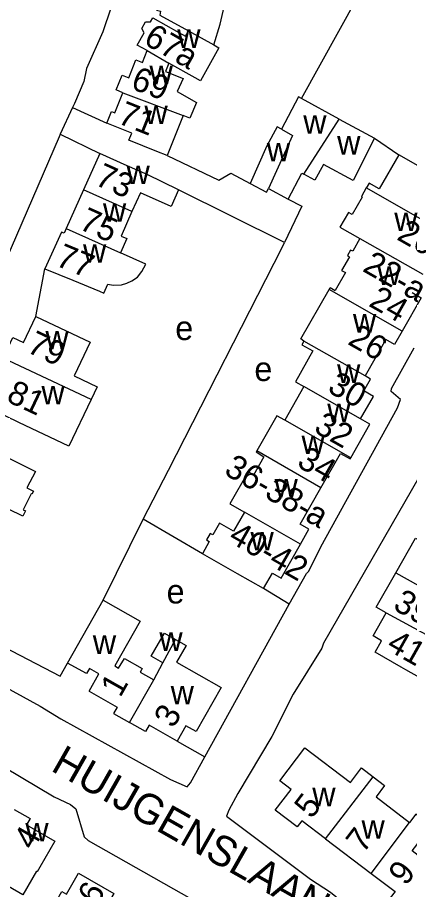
# Model space of a CAD drawing. Extents: x 159700 to 161346, y 381730 to 382922.
# Drawn here: x 160863.6 to 160928.7, y 382213.5 to 382358.4 of the extents above; entities that cross this region are included whole.
import ezdxf

# ---------------------------------------------------------------- set-up
doc = ezdxf.new("R2010")
doc.units = 0
for name, color, linetype in [('BLT_Basislijn', 7, 'Continuous'), ('BLT_Bebouwing', 7, 'Continuous'), ('BLT_Centroide', 7, 'Continuous'), ('BLT_Huisnummer', 7, 'Continuous'), ('BLT_Huisnummer_ tussenligend', 7, 'Continuous'), ('BLT_Huisnummer_reeks', 7, 'Continuous'), ('BLT_Onderverdeling_panden', 7, 'Continuous'), ('BLT_Straatnaam', 7, 'Continuous')]:
    doc.layers.add(name, color=color, linetype=linetype)

msp = doc.modelspace()

# ---------------------------------------------------------------- linework, layer by layer
at = {"layer": 'BLT_Basislijn'}
for p, q in [((160910.77, 382344.92), (160924.95, 382370.49)), ((160872.77, 382343.42), (160870.74, 382338.97)), ((160872.77, 382343.42), (160878.44, 382340.82)), ((160870.74, 382338.97), (160877.29, 382335.8)), ((160922.88, 382338.31), (160926.93, 382335.58)), ((160907.97, 382320.99), (160890.36, 382329.75)), ((160866.66, 382308.69), (160868.19, 382316.63)), ((160877.87, 382261.55), (160884.49, 382275.01)), ((160908.74, 382260.91), (160904.49, 382263.47)), ((160890.16, 382238.14), (160894.75, 382235.54))]:
    msp.add_line(p, q, dxfattribs=at)
for points in [[(160894.04, 382431.25), (160893.79, 382430.98), (160889.78, 382406.32), (160889.59, 382405.97), (160888.44, 382398.41), (160886.23, 382386.3), (160880.39, 382363.74), (160877.82, 382356.02), (160875.07, 382349.91), (160874.64, 382347.73), (160873.08, 382344.09), (160872.77, 382343.42)], [(160870.74, 382338.97), (160870.55, 382338.56), (160856.31, 382305.75), (160855.04, 382303.53), (160850.07, 382293.02), (160834.64, 382262.65)], [(160888.47, 382335.43), (160897.06, 382331.34), (160899.07, 382332.49), (160902.25, 382330.79)], [(160908.56, 382328.22), (160910.83, 382327.01), (160907.97, 382320.99)], [(160884.49, 382275.01), (160888.72, 382283.13), (160907.57, 382320.16), (160907.97, 382320.99)], [(160908.74, 382260.91), (160911.61, 382265.98), (160912.02, 382266.36), (160914.01, 382270.39), (160926.73, 382293.53), (160927.21, 382294.92), (160925.68, 382296.24), (160925.72, 382296.74), (160929.51, 382303.51)], [(160930.26, 382281.92), (160914.44, 382254.38), (160914.14, 382253.57), (160909.42, 382245.95), (160905.84, 382238.9), (160900.19, 382229.43), (160898.69, 382226.67), (160898.35, 382225.67), (160912.26, 382215.21), (160915.57, 382213.01), (160928.68, 382202.38), (160929.12, 382201.78)], [(160894.33, 382269.26), (160884.49, 382275.01)], [(160834.64, 382262.65), (160835.21, 382261.64), (160836.74, 382260.94), (160837.28, 382260.46), (160867.42, 382243.92), (160870.83, 382241.84), (160889.01, 382231.77), (160891.81, 382230.55), (160892.35, 382231.18), (160894.75, 382235.54)], [(160894.75, 382235.54), (160908.74, 382260.91)], [(160851.86, 382258.71), (160870.69, 382248.92), (160871.94, 382251.11)], [(160828.73, 382252.07), (160829.72, 382251.88), (160832.18, 382250.64), (160855.26, 382237.21), (160858.7, 382235.39), (160869.71, 382228.86), (160872.45, 382227.61), (160873.32, 382226.88), (160874.69, 382222.21), (160875.39, 382221.63), (160892.46, 382211.94), (160900.47, 382207.13), (160901.54, 382206.71), (160904.95, 382206.79), (160905.68, 382206.37), (160913.45, 382200), (160918.08, 382196.48), (160919.9, 382194.81), (160921.88, 382193.4), (160933.46, 382182.5)]]:
    msp.add_lwpolyline(points, dxfattribs=at)
at = {"layer": 'BLT_Bebouwing'}
for p, q in [((160917.04, 382341.5), (160910.77, 382344.92)), ((160917.04, 382341.5), (160922.88, 382338.31)), ((160877.29, 382335.8), (160874.59, 382329.74)), ((160874.59, 382329.74), (160871.71, 382323.31)), ((160905.29, 382329.96), (160908.56, 382328.22)), ((160911.15, 382297.07), (160908, 382291.47)), ((160908, 382291.47), (160906.7, 382292.21)), ((160914.01, 382280.21), (160917.28, 382285.94)), ((160886.26, 382248.31), (160887.76, 382251.13)), ((160891.59, 382240.66), (160890.16, 382238.14)), ((160914.76, 382221.89), (160922.33, 382216.14))]:
    msp.add_line(p, q, dxfattribs=at)
for points in [[(160896.24, 382353.85), (160897.26, 382357.29), (160898.66, 382363.29)], [(160886.7, 382359.59), (160887.39, 382359.44), (160887.24, 382358.78), (160892.02, 382356.17)], [(160885.17, 382352.88), (160883.52, 382353.81), (160884.67, 382355.86), (160884.26, 382356.56), (160884.89, 382357.68), (160885.71, 382357.68), (160886.08, 382358.35)], [(160886.08, 382358.35), (160890.44, 382355.89), (160891.52, 382355.28), (160892.02, 382356.17)], [(160896.24, 382353.85), (160897.08, 382353.34), (160894.02, 382347.88), (160893.13, 382348.35), (160888.77, 382350.82)], [(160881.12, 382345.89), (160880.01, 382346.34), (160880.99, 382348.78), (160882.09, 382348.34), (160883.3, 382351.34), (160884.38, 382350.91), (160885.17, 382352.88)], [(160888.77, 382350.82), (160888.2, 382349.41), (160891.12, 382348.23), (160890.15, 382346.06), (160893.34, 382344.26), (160892.23, 382341.68), (160891.16, 382342.11)], [(160878.44, 382340.82), (160879.22, 382342.77), (160879.77, 382342.55), (160881.12, 382345.89)], [(160910.77, 382344.92), (160910.3, 382345.18), (160907.46, 382339.85)], [(160891.16, 382342.11), (160888.47, 382335.43)], [(160888.47, 382335.43), (160886.77, 382336.11), (160882.13, 382337.98), (160882.6, 382339.14), (160878.44, 382340.82)], [(160907.46, 382339.85), (160906.73, 382340.24), (160905.03, 382337.05), (160902.25, 382330.79)], [(160922.88, 382338.31), (160919.35, 382331.29), (160914.41, 382333.95), (160913.02, 382331.35), (160911.15, 382332.34)], [(160890.36, 382329.75), (160885.16, 382332.29), (160881.86, 382333.76), (160877.29, 382335.8)], [(160926.93, 382335.58), (160923.7, 382329.91), (160922.01, 382330.87), (160921.53, 382330.04)], [(160934.62, 382322.59), (160937.51, 382327.66), (160933.16, 382330.13), (160930.11, 382331.87), (160930.93, 382333.3), (160926.93, 382335.58)], [(160908.56, 382328.22), (160910.85, 382332.51), (160911.15, 382332.34)], [(160890.36, 382329.75), (160889.13, 382326.99), (160884.04, 382329.26), (160882.64, 382326.14)], [(160902.25, 382330.79), (160904.96, 382329.34), (160905.29, 382329.96)], [(160921.52, 382330.05), (160920.72, 382328.63), (160920.85, 382328.55), (160919.18, 382325.64), (160918.56, 382326), (160917.85, 382324.76)], [(160882.64, 382326.14), (160880.83, 382322.07), (160881.8, 382321.64), (160880.74, 382319.28)], [(160917.85, 382324.76), (160917.15, 382323.52), (160920.48, 382321.63)], [(160871.71, 382323.31), (160871.36, 382322.52), (160870.91, 382322.72), (160868.19, 382316.63)], [(160920.48, 382321.63), (160919.29, 382319.54), (160918.93, 382319.74), (160918.4, 382318.81), (160918.74, 382318.61)], [(160868.19, 382316.63), (160872.81, 382314.72), (160877.23, 382312.88), (160877.96, 382312.58), (160878.63, 382314.06), (160879.54, 382313.9), (160880.92, 382313.97), (160881.8, 382314.21), (160882.64, 382314.61), (160883.56, 382315.25), (160884.3, 382316.18), (160884.91, 382317.41), (160880.74, 382319.28)], [(160918.74, 382318.61), (160917.44, 382316.33), (160918.06, 382315.98), (160916.37, 382313.02)], [(160911.17, 382304.57), (160910.66, 382304.96), (160915.35, 382313.2)], [(160915.35, 382313.2), (160915.52, 382313.5), (160916.37, 382313.02)], [(160929.16, 382312.68), (160930.67, 382311.82), (160927.51, 382306.27)], [(160861.25, 382301.79), (160862.88, 382305.23), (160864.63, 382304.4), (160866.66, 382308.69)], [(160866.66, 382308.69), (160875.69, 382304.42), (160873.04, 382298.82), (160876.85, 382297.02), (160875.85, 382294.92)], [(160927.51, 382306.27), (160926.23, 382304.03), (160924.78, 382304.86), (160921.36, 382298.86)], [(160911.17, 382304.57), (160910.85, 382304.01), (160912.67, 382302.97), (160909.76, 382297.85), (160911.15, 382297.07)], [(160920.59, 382291.69), (160922.71, 382295.42), (160921.14, 382296.32), (160922.25, 382298.26), (160921.36, 382298.86)], [(160875.85, 382294.92), (160872.18, 382287.16), (160863.87, 382291.1), (160859.35, 382293.23)], [(160906.7, 382292.21), (160903.39, 382286.39)], [(160918.96, 382285.23), (160922.13, 382290.81), (160920.59, 382291.69)], [(160855.02, 382287.81), (160858.43, 382286.08), (160858.84, 382286.88), (160863.3, 382284.62), (160864.51, 382284), (160866.63, 382282.93), (160865.2, 382280.2), (160866.28, 382279.65), (160866.02, 382279.15), (160865.89, 382279.21), (160864.56, 382276.59), (160864.94, 382276.4), (160864.49, 382275.5), (160862.13, 382276.69)], [(160903.39, 382286.39), (160903.28, 382286.2), (160904.53, 382285.36)], [(160904.53, 382285.36), (160902.81, 382282.35), (160901.91, 382282.86), (160898.88, 382277.54), (160901.29, 382276.16)], [(160917.28, 382285.94), (160918.85, 382285.05), (160918.96, 382285.23)], [(160910.6, 382270.85), (160912.01, 382273.34), (160910.57, 382274.16), (160914.01, 382280.21)], [(160901.29, 382276.16), (160899.51, 382273.03), (160897.16, 382274.36), (160896.04, 382272.39), (160895.6, 382272.63), (160895.01, 382271.58), (160895.46, 382271.33), (160894.33, 382269.26)], [(160926.44, 382266.11), (160929.69, 382271.85), (160931.36, 382270.91)], [(160904.49, 382263.47), (160905.94, 382266.02), (160907.38, 382265.2), (160910.6, 382270.85)], [(160904.49, 382263.47), (160900.15, 382265.94), (160894.33, 382269.26)], [(160924.83, 382259.45), (160923.2, 382260.38), (160926.44, 382266.11)], [(160871.94, 382251.11), (160877.87, 382261.55)], [(160877.87, 382261.55), (160884.02, 382258.09), (160879.77, 382250.63), (160880.4, 382250.28), (160881.39, 382251.87), (160884.35, 382250.2), (160884.23, 382250), (160884, 382249.6), (160886.26, 382248.31)], [(160932.63, 382247.45), (160928.11, 382250), (160927.35, 382250.43), (160922.99, 382252.9), (160924.08, 382254.82), (160922.66, 382255.62), (160924.83, 382259.45)], [(160887.76, 382251.13), (160885.82, 382252.23), (160888.01, 382256.09), (160889.87, 382255.03)], [(160889.87, 382255.03), (160891.62, 382254.04), (160890.03, 382251.25), (160897.45, 382247.04), (160893.28, 382239.7), (160891.59, 382240.66)], [(160875.52, 382246.42), (160877.16, 382249.32), (160875.57, 382250.21), (160875.08, 382249.34), (160871.94, 382251.11)], [(160875.52, 382246.42), (160880.16, 382243.78), (160879.57, 382242.73), (160882.23, 382241.22)], [(160890.16, 382238.14), (160885.5, 382240.79), (160884.88, 382239.7), (160882.23, 382241.22)], [(160914.76, 382221.89), (160910.83, 382224.88), (160910.06, 382223.88), (160906.43, 382226.64), (160909.05, 382230.08), (160907.18, 382231.51), (160911.36, 382237.01), (160918.93, 382231.26), (160920.75, 382233.67), (160922.67, 382232.21)], [(160922.67, 382232.21), (160924.58, 382230.76), (160923.17, 382228.89), (160928.71, 382224.61)], [(160863.1, 382226.77), (160865.71, 382225.26), (160865.11, 382224.22), (160869.81, 382221.52), (160867.32, 382217.18), (160866.9, 382216.43), (160866.76, 382216.51), (160864.52, 382212.6), (160857.32, 382216.76)], [(160922.33, 382216.14), (160926.31, 382213.12), (160925.52, 382212.09), (160929.12, 382209.36), (160932.04, 382213.16), (160934.37, 382211.37), (160939.01, 382217.4), (160933.9, 382221.33), (160931.43, 382218.12), (160929.17, 382219.88), (160932.34, 382224.04), (160929.76, 382226), (160928.71, 382224.61)], [(160873.88, 382202.77), (160872.97, 382201.18), (160865.7, 382205.37), (160868.46, 382210.2), (160869.09, 382209.84), (160871.01, 382213.13), (160871.75, 382212.7), (160873.75, 382216.18), (160879.62, 382212.8), (160878.53, 382210.91)]]:
    msp.add_lwpolyline(points, dxfattribs=at)
at = {"layer": 'BLT_Onderverdeling_panden'}
for p, q in [((160892.02, 382356.17), (160896.24, 382353.85)), ((160885.17, 382352.88), (160888.77, 382350.82)), ((160881.12, 382345.89), (160891.16, 382342.11)), ((160911.15, 382332.34), (160917.04, 382341.5)), ((160882.64, 382326.14), (160874.59, 382329.74)), ((160934.62, 382322.59), (160921.52, 382330.05)), ((160871.71, 382323.31), (160880.74, 382319.28)), ((160920.48, 382321.63), (160930.9, 382315.73)), ((160927.51, 382306.27), (160915.35, 382313.2)), ((160921.36, 382298.86), (160911.17, 382304.57)), ((160875.85, 382294.92), (160861.25, 382301.79)), ((160920.59, 382291.69), (160911.15, 382297.07)), ((160918.96, 382285.23), (160908, 382291.47)), ((160914.01, 382280.21), (160903.39, 382286.39)), ((160910.6, 382270.85), (160901.29, 382276.16)), ((160926.44, 382266.11), (160936.89, 382260.2)), ((160924.83, 382259.45), (160933.72, 382254.6)), ((160887.76, 382251.13), (160889.87, 382255.03)), ((160882.23, 382241.22), (160886.26, 382248.31)), ((160914.76, 382221.89), (160922.67, 382232.21)), ((160922.33, 382216.14), (160928.71, 382224.61))]:
    msp.add_line(p, q, dxfattribs=at)
msp.add_lwpolyline([(160907.46, 382339.85), (160909.27, 382338.8), (160905.29, 382329.96)], dxfattribs=at)

# ---------------------------------------------------------------- texts
at = {"layer": 'BLT_Centroide'}
for s, p in [('w', (160890.15, 382353.34)), ('w', (160885.55, 382347.28)), ('w', (160884.71, 382340.66)), ('w', (160911.07, 382339.07)), ('w', (160916.7, 382335.61)), ('w', (160905.02, 382334.46)), ('w', (160881.73, 382330.69)), ('w', (160877.82, 382324.44)), ('w', (160926.18, 382322.88)), ('w', (160874.51, 382317.62)), ('w', (160923.39, 382313.94)), ('w', (160919.32, 382306.03)), ('e', (160889.83, 382304.78)), ('w', (160868.27, 382303.23)), ('e', (160902.96, 382297.97)), ('w', (160916.69, 382297.66)), ('w', (160867.6, 382294.09)), ('w', (160915.05, 382291.16)), ('w', (160910.78, 382285.84)), ('w', (160906.3, 382278.62)), ('w', (160902.31, 382269.81)), ('e', (160888.39, 382261)), ('w', (160887.18, 382253.13)), ('w', (160876.14, 382252.61)), ('w', (160889.06, 382244.24)), ('w', (160912.57, 382227.31)), ('w', (160864.93, 382221.47)), ('w', (160920.74, 382221.91))]:
    msp.add_text(s, height=4, dxfattribs=at).set_placement(p)
at = {"layer": 'BLT_Huisnummer'}
for s, rotation, p in [('67a', 330.1385, (160884.37, 382354.11)), ('69', 339.7679, (160882.27, 382346.6)), ('71', 338.0518, (160880.06, 382340.9)), ('73', 335.9241, (160876.28, 382330.68)), ('20c', 330.3291, (160926.42, 382321.58)), ('77', 337.4921, (160869.77, 382317.25)), ('26', 330.333, (160918.28, 382304.18)), ('79', 334.6938, (160864.97, 382302.88)), ('30', 330.321, (160914.9, 382296.29)), ('81', 334.7007, (160861.59, 382294.69)), ('34', 330.3188, (160909.82, 382283.88)), ('41', 330.4768, (160924.7, 382253.41)), ('1', 60.37, (160880.68, 382245.24)), ('3', 60.3642, (160889.53, 382240.13)), ('5', 52.7065, (160912.45, 382225.07)), ('4', 60.1172, (160866.23, 382219.85)), ('9', 52.7612, (160928.09, 382213.93)), ('6', 59.9094, (160876.84, 382210.64))]:
    msp.add_text(s, height=4, rotation=rotation, dxfattribs=at).set_placement(p)
at = {"layer": 'BLT_Huisnummer_ tussenligend'}
for s, rotation, p in [('75', 335.9241, (160873.65, 382323.32)), ('32', 330.321, (160912.64, 382289.62)), ('39', 330.4795, (160925.78, 382260.14)), ('7', 52.7037, (160921.04, 382219.34))]:
    msp.add_text(s, height=4, rotation=rotation, dxfattribs=at).set_placement(p)
at = {"layer": 'BLT_Huisnummer_reeks'}
for s, rotation, p in [('22-a', 330.3394, (160920.74, 382316.32)), ('24', 330.3394, (160921.76, 382310.53)), ('36-38-a', 330.3162, (160897.74, 382282.56)), ('40-42', 330.2742, (160898.45, 382271.37))]:
    msp.add_text(s, height=4, rotation=rotation, dxfattribs=at).set_placement(p)
at = {"layer": 'BLT_Straatnaam'}
msp.add_text('HUIJGENSLAAN', height=5, rotation=330.4263, dxfattribs=at).set_placement((160868.99, 382233.31))

doc.saveas('drawing.dxf')
